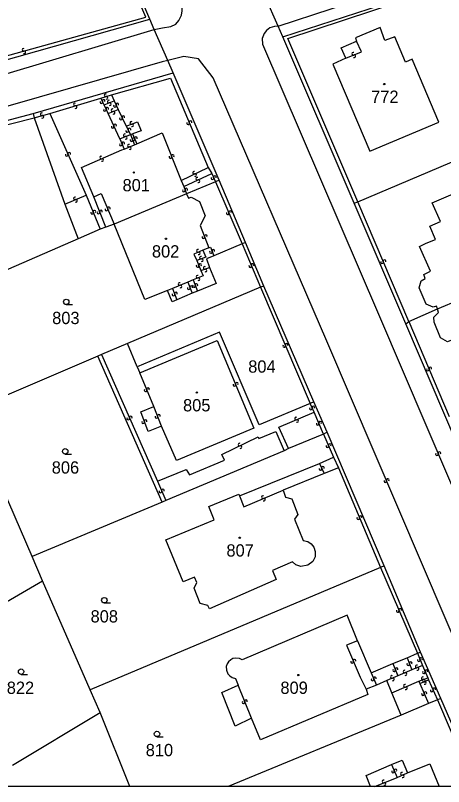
# Model space of a CAD drawing. Extents: x -600391 to -599491, y -1160176 to -1159402.
# Drawn here: x -599951.3 to -599892, y -1160176.1 to -1160069.3 of the extents above; entities that cross this region are included whole.
import ezdxf

# ---------------------------------------------------------------- set-up
doc = ezdxf.new("R2010")
doc.units = 0
for name, color, linetype in [('Level 1', 7, 'Continuous'), ('Level 13', 7, 'Continuous'), ('Level 3', 7, 'Continuous'), ('Level 4', 7, 'Continuous'), ('Level 5', 7, 'Continuous'), ('Vrstva 63', 7, 'Continuous')]:
    doc.layers.add(name, color=color, linetype=linetype)

msp = doc.modelspace()

# ---------------------------------------------------------------- linework, layer by layer
at = {"layer": 'Level 1'}
for p, q in [((-599887.13, -1160176.08), (-599892.35, -1160163.9)), ((-599935.46, -1160176.08), (-599939.58, -1160165.83)), ((-599897.88, -1160166.18), (-599921.81, -1160176.08))]:
    msp.add_line(p, q, dxfattribs=at)
for points in [[(-599932.7, -1160069.8), (-599940.17, -1160052.22)], [(-599914.24, -1160072.24), (-599890.32, -1160064.42), (-599879.7, -1160060.63), (-599875.46, -1160059.11)], [(-599914.89, -1160070.76), (-599916.7, -1160066.63)], [(-599966.81, -1160079.43), (-599932.7, -1160069.8)], [(-599932.07, -1160071.24), (-599932.7, -1160069.8)], [(-599914.24, -1160072.24), (-599914.89, -1160070.76)], [(-599905.51, -1160075.18), (-599907.33, -1160076.01), (-599902.19, -1160088.08), (-599892.63, -1160084.07), (-599896.35, -1160075.33), (-599897.24, -1160075.72), (-599898.76, -1160072.22), (-599900.11, -1160072.76), (-599900.78, -1160070.96), (-599904.19, -1160072.37), (-599904.06, -1160072.84)], [(-599930.21, -1160075.52), (-599932.07, -1160071.24)], [(-599904.37, -1160095.29), (-599914.24, -1160072.24)], [(-599905.51, -1160075.18), (-599906.19, -1160073.77), (-599904.06, -1160072.84)], [(-599929.47, -1160077.23), (-599930.21, -1160075.52)], [(-599948.86, -1160082.86), (-599929.47, -1160077.23)], [(-599923.07, -1160092.08), (-599929.47, -1160077.23)], [(-599903.88, -1160095.09), (-599867.15, -1160079.55)], [(-599967.37, -1160087.73), (-599948.86, -1160082.86)], [(-599948.86, -1160082.86), (-599948.69, -1160083.45)], [(-599948.69, -1160083.45), (-599944.46, -1160095.39)], [(-599923.59, -1160092.3), (-599927.61, -1160093.97)], [(-599923.07, -1160092.08), (-599923.59, -1160092.3)], [(-599919.42, -1160100.71), (-599923.07, -1160092.08)], [(-599892.82, -1160109.92), (-599892.99, -1160109.52), (-599893.45, -1160109.7), (-599894.41, -1160109.24), (-599895.35, -1160107), (-599895.07, -1160106.05), (-599894.52, -1160105.7), (-599894.72, -1160105.13), (-599893.81, -1160104.7), (-599895.32, -1160101.27), (-599894.41, -1160100.82), (-599893.12, -1160100.3), (-599893.91, -1160098.46), (-599892.4, -1160097.81), (-599893.55, -1160095.22), (-599887.76, -1160092.71), (-599885.76, -1160097.2)], [(-599927.61, -1160093.97), (-599937.64, -1160098.18)], [(-599944.46, -1160095.39), (-599942.6, -1160100.22)], [(-599904.37, -1160095.29), (-599903.88, -1160095.09)], [(-599897.21, -1160111.98), (-599904.37, -1160095.29)], [(-599939.54, -1160098.88), (-599942.6, -1160100.22)], [(-599938.8, -1160098.61), (-599939.54, -1160098.88)], [(-599937.64, -1160098.18), (-599938.8, -1160098.61)], [(-599930.25, -1160107.35), (-599933.38, -1160108.63), (-599937.64, -1160098.18)], [(-599942.6, -1160100.22), (-599961.96, -1160108.61)], [(-599919.87, -1160100.9), (-599923.82, -1160102.56)], [(-599919.42, -1160100.71), (-599919.87, -1160100.9)], [(-599916.87, -1160106.76), (-599919.42, -1160100.71)], [(-599923.82, -1160102.56), (-599924.84, -1160102.96), (-599924.4, -1160104.2)], [(-599924.4, -1160104.2), (-599923.5, -1160106.4), (-599926.1, -1160107.44)], [(-599892.82, -1160109.92), (-599883.54, -1160106.05)], [(-599917.33, -1160106.92), (-599935.76, -1160114.73)], [(-599928.92, -1160108.65), (-599929.58, -1160108.96), (-599930.25, -1160107.35)], [(-599926.1, -1160107.44), (-599926.8, -1160107.75)], [(-599916.87, -1160106.76), (-599917.33, -1160106.92)], [(-599909.98, -1160122.78), (-599916.87, -1160106.76)], [(-599926.8, -1160107.75), (-599928.92, -1160108.65)], [(-599896.79, -1160111.65), (-599892.82, -1160109.92)], [(-599897.21, -1160111.98), (-599896.79, -1160111.65)], [(-599890.2, -1160128.43), (-599897.21, -1160111.98)], [(-599910.46, -1160123.03), (-599917.53, -1160125.98), (-599923.02, -1160113.14), (-599934.43, -1160117.93)], [(-599935.76, -1160114.73), (-599939.38, -1160116.25)], [(-599934.43, -1160117.93), (-599935.76, -1160114.73)], [(-599939.9, -1160116.45), (-599957.71, -1160124.07)], [(-599939.38, -1160116.25), (-599939.9, -1160116.45)], [(-599930.98, -1160136.69), (-599939.9, -1160116.45)], [(-599909.98, -1160122.78), (-599910.46, -1160123.03)], [(-599908.1, -1160126.99), (-599909.98, -1160122.78)], [(-599908.6, -1160127.26), (-599913.49, -1160129.26)], [(-599908.1, -1160126.99), (-599908.6, -1160127.26)], [(-599900.24, -1160145.51), (-599908.1, -1160126.99)], [(-599948.99, -1160144.22), (-599955.5, -1160129.24)], [(-599914.07, -1160129.57), (-599930.47, -1160136.47)], [(-599913.49, -1160129.26), (-599914.07, -1160129.57)], [(-599909.2, -1160131.31), (-599907.23, -1160130.47)], [(-599907.23, -1160130.47), (-599906.56, -1160131.94)], [(-599920.24, -1160135.83), (-599909.2, -1160131.31)], [(-599906.56, -1160131.94), (-599908.55, -1160132.71)], [(-599908.55, -1160132.71), (-599914.23, -1160135.01)], [(-599914.23, -1160135.01), (-599913.89, -1160136), (-599913.02, -1160136.23), (-599912.19, -1160138.38), (-599912.64, -1160139.06), (-599911.44, -1160141.99), (-599910.81, -1160142.14), (-599910.34, -1160142.45), (-599909.97, -1160142.91), (-599909.76, -1160143.5), (-599909.8, -1160144.26), (-599910.11, -1160144.9), (-599910.78, -1160145.43), (-599911.75, -1160145.59), (-599912.44, -1160145.37), (-599912.92, -1160144.97), (-599915.67, -1160146.16), (-599915.16, -1160147.38), (-599924.42, -1160151.46), (-599924.65, -1160151.02), (-599925.69, -1160150.71), (-599926.55, -1160148.61), (-599926.15, -1160147.79), (-599926.5, -1160147.06), (-599928.07, -1160147.73), (-599930.48, -1160141.92), (-599923.75, -1160139.13), (-599924.49, -1160137.27), (-599920.33, -1160135.56), (-599920.24, -1160135.83)], [(-599930.98, -1160136.69), (-599948.99, -1160144.22)], [(-599930.47, -1160136.47), (-599930.98, -1160136.69)], [(-599947.56, -1160147.56), (-599948.99, -1160144.22)], [(-599900.73, -1160145.73), (-599940.94, -1160162.69)], [(-599900.24, -1160145.51), (-599900.73, -1160145.73)], [(-599895.17, -1160157.44), (-599900.24, -1160145.51)], [(-599961.7, -1160155.81), (-599947.56, -1160147.56)], [(-599940.94, -1160162.69), (-599947.56, -1160147.56)], [(-599903.91, -1160155.87), (-599905.35, -1160152.33), (-599919.9, -1160158.52), (-599920.28, -1160158.33), (-599920.75, -1160158.28), (-599921.17, -1160158.36), (-599921.48, -1160158.51), (-599921.77, -1160158.78), (-599921.97, -1160159.09), (-599922.09, -1160159.45), (-599922.08, -1160159.95), (-599921.88, -1160160.45), (-599921.61, -1160160.75), (-599921.26, -1160160.97), (-599920.83, -1160161.09), (-599920.46, -1160162.04)], [(-599903.91, -1160155.87), (-599902.04, -1160160.33)], [(-599897.05, -1160158.23), (-599895.61, -1160157.62)], [(-599895.61, -1160157.62), (-599895.17, -1160157.44)], [(-599892.35, -1160163.9), (-599895.17, -1160157.44)], [(-599899, -1160159.05), (-599897.05, -1160158.23)], [(-599902.04, -1160160.33), (-599899, -1160159.05)], [(-599899.83, -1160161.38), (-599901.27, -1160162.01)], [(-599899.14, -1160163.08), (-599899.83, -1160161.38)], [(-599939.58, -1160165.83), (-599940.94, -1160162.69)], [(-599918.6, -1160166.62), (-599920.86, -1160167.69), (-599922.73, -1160163.07), (-599920.46, -1160162.04)], [(-599902.72, -1160162.59), (-599902.47, -1160163.32), (-599917.36, -1160169.59), (-599918.6, -1160166.62)], [(-599901.27, -1160162.01), (-599902.72, -1160162.59)], [(-599897.88, -1160166.18), (-599899.14, -1160163.08)], [(-599892.83, -1160164.06), (-599894.09, -1160164.58)], [(-599892.35, -1160163.9), (-599892.83, -1160164.06)], [(-599894.09, -1160164.58), (-599897.88, -1160166.18)], [(-599951.71, -1160173.12), (-599939.58, -1160165.83)], [(-599899.19, -1160173.04), (-599897.74, -1160172.4), (-599896.97, -1160174.17)], [(-599902.11, -1160176.08), (-599902.72, -1160174.53), (-599899.19, -1160173.04)], [(-599896.97, -1160174.17), (-599893.87, -1160172.91), (-599892.58, -1160176.08)]]:
    msp.add_lwpolyline(points, dxfattribs=at)
at = {"layer": 'Level 13'}
for centre, start, end in [((-599950.18, -1160074.02), 52.9231, 285.0211), ((-599950.08, -1160074.38), 232.7086, 105.2986), ((-599904.5, -1160074.58), 59.2197, 291.3177), ((-599904.36, -1160074.92), 239.0052, 111.5952), ((-599938.81, -1160080.32), 55.3419, 287.4399), ((-599938.69, -1160080.68), 235.1274, 107.7174), ((-599943.07, -1160081.61), 53.8854, 285.9834), ((-599942.97, -1160081.97), 233.6709, 106.2609), ((-599939.4, -1160081.29), 155.4129, 27.5109), ((-599939.08, -1160081.11), 335.1984, 207.7884), ((-599938.38, -1160081.21), 59.6055, 291.7035), ((-599938.24, -1160081.55), 239.391, 111.981), ((-599937.52, -1160081.78), 151.9934, 24.5834), ((-599937.18, -1160081.62), 332.2079, 204.3059), ((-599947.67, -1160082.96), 53.4588, 285.5568), ((-599938.91, -1160082.33), 151.2022, 23.3002), ((-599938.57, -1160082.19), 330.9877, 203.5777), ((-599937.84, -1160082.41), 58.8205, 290.9185), ((-599937.7, -1160082.75), 238.606, 111.196), ((-599947.57, -1160083.32), 233.2444, 105.8344), ((-599936.69, -1160083.54), 152.7182, 25.3082), ((-599936.35, -1160083.38), 332.9327, 205.0307), ((-599935.25, -1160084.15), 57.7676, 289.8656), ((-599927.04, -1160084.07), 330.2581, 202.3561), ((-599937.83, -1160084.68), 152.4707, 24.5687), ((-599937.49, -1160084.52), 332.2562, 204.8462), ((-599935.5, -1160085.09), 336.2992, 208.3972), ((-599935.13, -1160084.49), 237.5532, 110.1432), ((-599927.38, -1160084.21), 150.0436, 22.6336), ((-599936.16, -1160085.87), 58.8441, 290.9421), ((-599936.02, -1160086.21), 238.6296, 111.2196), ((-599935.82, -1160085.27), 156.0847, 28.6747), ((-599934.61, -1160086.29), 331.024, 203.122), ((-599936.7, -1160087.13), 150.1163, 22.7063), ((-599936.36, -1160086.99), 330.3308, 202.4288), ((-599935.59, -1160087.31), 59.7932, 291.8912), ((-599935.24, -1160086.53), 147.7143, 20.3043), ((-599934.95, -1160086.43), 150.8096, 23.3996), ((-599934.9, -1160086.41), 327.9288, 200.0268), ((-599943.85, -1160088.43), 331.3352, 203.4332), ((-599935.45, -1160087.65), 239.5787, 112.1687), ((-599944.19, -1160088.57), 151.1208, 23.7108), ((-599939.42, -1160088.95), 60.8301, 292.9281), ((-599939.28, -1160089.29), 240.6157, 113.2057), ((-599929.84, -1160088.88), 148.8099, 21.3999), ((-599929.5, -1160088.74), 329.0243, 201.1223), ((-599926.56, -1160091.05), 62.647, 294.745), ((-599926.4, -1160091.39), 242.4325, 115.0225), ((-599926.12, -1160091.89), 61.9608, 294.0588), ((-599925.96, -1160092.23), 241.7463, 114.3363), ((-599924.01, -1160091.8), 151.4492, 24.0392), ((-599923.67, -1160091.66), 331.6637, 203.7617), ((-599927.97, -1160093.52), 147.5911, 20.1811), ((-599927.63, -1160093.4), 327.8056, 199.9036), ((-599943.05, -1160094.61), 59.7723, 291.8703), ((-599942.91, -1160094.95), 239.5579, 112.1479), ((-599940.69, -1160096.59), 149.7522, 22.3422), ((-599940.35, -1160096.45), 329.9667, 202.0647), ((-599939.79, -1160096.57), 148.5644, 20.6624), ((-599939.45, -1160096.43), 328.3499, 200.9399), ((-599938.69, -1160096.13), 149.7686, 22.3586), ((-599938.35, -1160095.99), 329.983, 202.081), ((-599921.9, -1160096.67), 150.5496, 23.1396), ((-599921.56, -1160096.53), 330.764, 202.862), ((-599925.27, -1160099.99), 148.8309, 21.4209), ((-599924.93, -1160099.85), 329.0453, 201.1433), ((-599926.03, -1160101.87), 61.6713, 294.2613), ((-599925.88, -1160102.21), 241.8857, 113.9837), ((-599924.23, -1160102.03), 148.7962, 21.3862), ((-599923.89, -1160101.89), 329.0107, 201.1087), ((-599925.6, -1160102.83), 57.8172, 290.4072), ((-599925.48, -1160103.17), 238.0316, 110.1296), ((-599900.17, -1160103.3), 330.336, 202.926), ((-599926.06, -1160103.97), 148.0828, 20.6728), ((-599925.72, -1160103.85), 328.2972, 200.3952), ((-599925.07, -1160104.22), 54.9652, 287.0632), ((-599918.77, -1160103.98), 150.0345, 22.6245), ((-599918.43, -1160103.84), 330.2489, 202.3469), ((-599900.51, -1160103.44), 150.5504, 22.6484), ((-599926.07, -1160105.45), 59.4554, 292.0454), ((-599924.97, -1160104.58), 234.7507, 107.3407), ((-599928.57, -1160106.47), 59.3759, 291.9659), ((-599926.23, -1160106.61), 328.3354, 200.4334), ((-599925.93, -1160105.79), 239.6699, 111.7679), ((-599928.43, -1160106.81), 239.5903, 111.6883), ((-599927.29, -1160107.05), 149.2776, 21.8676), ((-599926.95, -1160106.91), 329.4921, 201.5901), ((-599926.57, -1160106.74), 148.121, 20.711), ((-599929.41, -1160107.93), 149.2093, 21.7993), ((-599929.07, -1160107.79), 329.4238, 201.5218), ((-599914.07, -1160115.05), 150.2538, 22.8438), ((-599913.73, -1160114.91), 330.4682, 202.5662), ((-599893.83, -1160118.17), 330.3559, 202.4539), ((-599894.17, -1160118.31), 150.1414, 22.7314), ((-599920.63, -1160120.3), 330.1133, 202.2113), ((-599933.27, -1160121.19), 150.1237, 22.2217), ((-599932.93, -1160121.05), 329.9093, 202.4993), ((-599920.97, -1160120.44), 149.8989, 22.4889), ((-599910.03, -1160123.57), 330.8125, 203.4025), ((-599931.43, -1160124.73), 328.4494, 201.0394), ((-599910.37, -1160123.71), 151.0269, 23.1249), ((-599935.67, -1160125.09), 151.0237, 23.6137), ((-599935.33, -1160124.95), 331.2382, 203.3362), ((-599933.61, -1160125.6), 147.9983, 20.0963), ((-599933.27, -1160125.48), 327.7838, 200.3738), ((-599931.77, -1160124.87), 148.6639, 20.7619), ((-599912.43, -1160125.1), 60.4431, 292.5411), ((-599912.29, -1160125.44), 240.2287, 112.8187), ((-599909.09, -1160125.68), 330.9268, 203.5168), ((-599909.43, -1160125.82), 151.1413, 23.2393), ((-599920.27, -1160128.71), 63.4776, 295.5756), ((-599908.09, -1160128.93), 150.2706, 22.8606), ((-599907.75, -1160128.79), 330.4851, 202.5831), ((-599920.11, -1160129.05), 243.2631, 115.8531), ((-599892.57, -1160129.9), 330.557, 202.655), ((-599892.91, -1160130.04), 150.3425, 22.9325), ((-599909.05, -1160132.09), 152.063, 24.653), ((-599908.71, -1160131.93), 332.2775, 204.3755), ((-599900.05, -1160133.76), 150.5463, 22.6443), ((-599899.71, -1160133.62), 330.3318, 202.9218), ((-599931.21, -1160135.2), 150.3827, 22.9727), ((-599930.87, -1160135.06), 330.5971, 202.6951), ((-599917.01, -1160135.99), 60.405, 292.503), ((-599916.87, -1160136.33), 240.1905, 112.7805), ((-599903.81, -1160138.91), 150.0755, 22.6655), ((-599903.47, -1160138.77), 330.2899, 202.3879), ((-599898.34, -1160151.75), 150.4557, 23.0457), ((-599898, -1160151.61), 330.6701, 202.7681), ((-599904.66, -1160158.78), 150.3879, 22.9779), ((-599904.32, -1160158.64), 330.6024, 202.7004), ((-599895.43, -1160158.55), 149.4203, 22.0103), ((-599895.09, -1160158.41), 329.6348, 201.7328), ((-599898.49, -1160159.83), 329.291, 201.389), ((-599896.88, -1160159.13), 149.4342, 22.0242), ((-599896.54, -1160158.99), 329.6486, 201.7466), ((-599895.71, -1160159.44), 58.1432, 290.7332), ((-599895.58, -1160159.78), 238.3576, 110.4556), ((-599899.14, -1160160.89), 60.1275, 292.7175), ((-599898.83, -1160159.97), 149.0765, 21.6665), ((-599897.41, -1160160.15), 60.7105, 293.3005), ((-599897.27, -1160160.49), 240.925, 113.023), ((-599894.87, -1160161.08), 58.6004, 290.6984), ((-599894.72, -1160160.25), 150.234, 22.824), ((-599894.38, -1160160.11), 330.4485, 202.5465), ((-599901.83, -1160161.25), 151.7818, 24.3718), ((-599901.49, -1160161.09), 331.9963, 204.0943), ((-599899, -1160161.23), 240.342, 112.44), ((-599897.34, -1160162.12), 60.4047, 292.5027), ((-599894.73, -1160161.39), 60.5713, 292.6693), ((-599894.73, -1160161.42), 238.3859, 110.9759), ((-599894.59, -1160161.73), 240.3569, 112.9469), ((-599897.2, -1160162.46), 240.1903, 112.7803), ((-599894.51, -1160163.13), 330.3455, 202.4435), ((-599893.62, -1160162.75), 151.4293, 24.0193), ((-599893.28, -1160162.61), 331.6438, 203.7418), ((-599919.36, -1160164.26), 329.261, 201.851), ((-599894.85, -1160163.27), 150.131, 22.721), ((-599919.7, -1160164.4), 149.4755, 21.5735), ((-599898.65, -1160173.85), 330.4534, 202.5513), ((-599898.99, -1160173.99), 150.2389, 22.8289), ((-599897.78, -1160174.31), 60.5713, 292.6693), ((-599897.64, -1160174.65), 240.3569, 112.9469), ((-599900.31, -1160175.37), 59.9132, 292.0112), ((-599900.17, -1160175.71), 239.6988, 112.2888)]:
    msp.add_arc(centre, 0.184, start, end, dxfattribs=at)
at = {"layer": 'Level 3'}
for p, q in [((-599892.83, -1160164.06), (-599887.73, -1160176.08)), ((-599901.52, -1160176.08), (-599898.44, -1160174.8))]:
    msp.add_line(p, q, dxfattribs=at)
for points in [[(-599932.07, -1160071.24), (-599930.91, -1160071.01), (-599929.76, -1160070.79), (-599929.09, -1160070.48), (-599928.67, -1160069.97), (-599928.31, -1160069.23), (-599928.2, -1160068.62), (-599928.16, -1160067.74), (-599944.31, -1160030.32), (-599957.81, -1159998.89), (-599969.74, -1159971.09), (-599971.59, -1159969.36), (-599973.79, -1159968.78), (-599975.69, -1159969.42)], [(-599914.89, -1160070.76), (-599907.55, -1160068.37), (-599900.91, -1160066.15), (-599873.39, -1160056.47), (-599862.7, -1160052.44), (-599839.71, -1160043.28), (-599838.86, -1160042.68)], [(-599967.02, -1160078.9), (-599933.24, -1160069.5), (-599940.38, -1160052.87)], [(-599903.88, -1160095.09), (-599913.57, -1160072.45), (-599890.16, -1160064.71), (-599879.57, -1160060.98), (-599875.41, -1160059.5)], [(-599914.89, -1160070.76), (-599915.43, -1160070.79), (-599916.05, -1160071.01), (-599916.5, -1160071.34), (-599916.83, -1160071.76), (-599917.11, -1160072.47), (-599917.09, -1160073.24), (-599901.01, -1160110.66), (-599884.47, -1160149.28), (-599878.82, -1160162.53), (-599872.95, -1160176.08)], [(-600027.74, -1160093.03), (-600026.82, -1160093.42), (-600025.86, -1160093.71), (-600021.64, -1160093.67), (-600010.66, -1160091.41), (-599968.6, -1160081.73), (-599953.35, -1160077.6), (-599932.07, -1160071.24)], [(-599905.51, -1160075.18), (-599903.34, -1160074.31), (-599904.06, -1160072.84)], [(-599881.72, -1160176.08), (-599891.61, -1160153.01), (-599908.15, -1160114.37), (-599923.89, -1160077.89), (-599925.96, -1160075.27), (-599927.96, -1160074.98), (-599930.21, -1160075.52)], [(-599930.21, -1160075.52), (-599930.99, -1160075.71), (-599952.34, -1160081.82), (-599967.7, -1160085.82), (-600009.32, -1160095.04), (-600022.67, -1160102.5), (-600023.09, -1160102.76)], [(-599938.01, -1160080.26), (-599929.82, -1160077.94), (-599924.59, -1160090.33)], [(-599946.54, -1160082.83), (-599939.49, -1160080.74)], [(-599939.49, -1160080.74), (-599938.01, -1160080.26)], [(-599939, -1160081.66), (-599939.49, -1160080.74)], [(-599938.01, -1160080.26), (-599937.63, -1160081.1)], [(-599939, -1160081.66), (-599937.63, -1160081.1)], [(-599938.47, -1160082.86), (-599939, -1160081.66)], [(-599937.63, -1160081.1), (-599937.07, -1160082.31)], [(-599948.69, -1160083.45), (-599946.54, -1160082.83)], [(-599946.54, -1160082.83), (-599941.5, -1160094.17)], [(-599938.47, -1160082.86), (-599937.07, -1160082.31)], [(-599936.84, -1160086.34), (-599938.47, -1160082.86)], [(-599937.07, -1160082.31), (-599935.97, -1160084.61)], [(-599967.31, -1160088.16), (-599948.69, -1160083.45)], [(-599935.97, -1160084.61), (-599934.41, -1160084.03), (-599933.89, -1160085.25), (-599935.08, -1160085.67)], [(-599935.97, -1160084.61), (-599935.34, -1160085.75)], [(-599936.84, -1160086.34), (-599935.34, -1160085.75)], [(-599935.34, -1160085.75), (-599935.08, -1160085.67)], [(-599935.34, -1160085.75), (-599934.8, -1160087.19)], [(-599935.08, -1160085.67), (-599934.48, -1160087.04)], [(-599934.48, -1160087.04), (-599930.98, -1160085.51), (-599928.36, -1160092.11)], [(-599936.84, -1160086.34), (-599936.23, -1160087.78)], [(-599936.23, -1160087.78), (-599934.8, -1160087.19)], [(-599934.8, -1160087.19), (-599934.48, -1160087.04)], [(-599940.44, -1160094.38), (-599942.15, -1160090.33), (-599936.55, -1160087.9), (-599936.23, -1160087.78)], [(-599928.36, -1160092.11), (-599924.59, -1160090.33)], [(-599924.59, -1160090.33), (-599924.1, -1160091.17)], [(-599927.99, -1160092.95), (-599924.1, -1160091.17)], [(-599924.1, -1160091.17), (-599923.59, -1160092.3)], [(-599928.36, -1160092.11), (-599927.99, -1160092.95)], [(-599923.59, -1160092.3), (-599919.87, -1160100.9)], [(-599927.99, -1160092.95), (-599927.61, -1160093.97)], [(-599944.46, -1160095.39), (-599941.5, -1160094.17)], [(-599941.5, -1160094.17), (-599939.54, -1160098.88)], [(-599940.44, -1160094.38), (-599939.41, -1160093.93), (-599937.64, -1160098.18)], [(-599938.8, -1160098.61), (-599940.44, -1160094.38)], [(-599927.61, -1160093.97), (-599927.31, -1160094.58), (-599926.95, -1160094.43), (-599925.8, -1160095.02), (-599925.02, -1160097.01), (-599925.71, -1160098.38), (-599924.49, -1160101.45)], [(-599896.79, -1160111.65), (-599903.88, -1160095.09)], [(-599919.87, -1160100.9), (-599917.33, -1160106.92)], [(-599925.32, -1160101.76), (-599926.57, -1160102.33), (-599926.15, -1160103.23)], [(-599925.32, -1160101.76), (-599924.93, -1160102.77), (-599926.15, -1160103.23)], [(-599924.49, -1160101.45), (-599925.32, -1160101.76)], [(-599924.49, -1160101.45), (-599924.3, -1160101.35), (-599923.82, -1160102.56)], [(-599926.15, -1160103.23), (-599925.63, -1160104.59)], [(-599925.63, -1160104.59), (-599924.4, -1160104.2)], [(-599925.63, -1160104.59), (-599925.3, -1160105.33), (-599926.69, -1160105.9)], [(-599927.43, -1160106.2), (-599929.56, -1160107.07)], [(-599926.69, -1160105.9), (-599927.43, -1160106.2)], [(-599927.43, -1160106.2), (-599926.8, -1160107.75)], [(-599926.69, -1160105.9), (-599926.1, -1160107.44)], [(-599929.56, -1160107.07), (-599930.25, -1160107.35)], [(-599929.56, -1160107.07), (-599928.92, -1160108.65)], [(-599917.33, -1160106.92), (-599910.46, -1160123.03)], [(-599885.93, -1160117.4), (-599886.05, -1160117.06), (-599888.14, -1160117.9), (-599889.67, -1160114.41), (-599890.6, -1160114.85), (-599890.89, -1160114.25), (-599891.46, -1160114.5), (-599892.41, -1160113.94), (-599893.3, -1160111.75), (-599893.35, -1160111.05), (-599892.67, -1160110.4), (-599892.82, -1160109.92)], [(-599896.79, -1160111.65), (-599891.2, -1160124.83)], [(-599934.08, -1160118.79), (-599923.34, -1160114.31), (-599918.26, -1160126.43), (-599928.97, -1160130.91), (-599931.07, -1160126.16)], [(-599939.38, -1160116.25), (-599931.62, -1160133.79)], [(-599934.43, -1160117.93), (-599934.08, -1160118.79)], [(-599932.13, -1160123.44), (-599934.08, -1160118.79)], [(-599931.07, -1160126.16), (-599932.93, -1160126.89), (-599933.95, -1160124.18), (-599932.13, -1160123.44)], [(-599931.07, -1160126.16), (-599932.13, -1160123.44)], [(-599909.93, -1160124.24), (-599910.46, -1160123.03)], [(-599913.49, -1160129.26), (-599914.79, -1160126.31), (-599909.93, -1160124.24)], [(-599908.6, -1160127.26), (-599909.93, -1160124.24)], [(-599931.62, -1160133.79), (-599927.63, -1160132.18), (-599927.19, -1160132.89), (-599922.36, -1160130.87), (-599922.69, -1160130.1), (-599917.69, -1160127.65), (-599917.59, -1160127.87), (-599915.24, -1160126.92), (-599914.07, -1160129.57)], [(-599908.6, -1160127.26), (-599907.23, -1160130.47)], [(-599909.2, -1160131.31), (-599908.55, -1160132.71)], [(-599906.56, -1160131.94), (-599900.73, -1160145.73)], [(-599931.62, -1160133.79), (-599930.47, -1160136.47)], [(-599920.24, -1160135.83), (-599919.64, -1160137.31), (-599914.23, -1160135.01)], [(-599900.73, -1160145.73), (-599895.61, -1160157.62)], [(-599903.91, -1160155.87), (-599905.44, -1160156.49), (-599903.53, -1160160.94), (-599902.72, -1160162.59)], [(-599895.61, -1160157.62), (-599894.91, -1160159.33)], [(-599897.05, -1160158.23), (-599896.37, -1160159.89)], [(-599899, -1160159.05), (-599898.32, -1160160.74)], [(-599894.91, -1160159.33), (-599896.37, -1160159.89)], [(-599894.91, -1160159.33), (-599894.19, -1160161.02)], [(-599902.04, -1160160.33), (-599901.27, -1160162.01)], [(-599898.32, -1160160.74), (-599899.83, -1160161.38)], [(-599896.37, -1160159.89), (-599898.32, -1160160.74)], [(-599899.14, -1160163.08), (-599895.4, -1160161.49)], [(-599895.4, -1160161.49), (-599894.19, -1160161.02)], [(-599895.4, -1160161.49), (-599895.26, -1160161.82)], [(-599895.26, -1160161.82), (-599894.07, -1160161.31)], [(-599895.26, -1160161.82), (-599894.09, -1160164.58)], [(-599894.19, -1160161.02), (-599894.07, -1160161.31)], [(-599894.07, -1160161.31), (-599892.83, -1160164.06)], [(-599918.6, -1160166.62), (-599920.46, -1160162.04)], [(-599899.19, -1160173.04), (-599898.44, -1160174.8)], [(-599898.44, -1160174.8), (-599896.97, -1160174.17)]]:
    msp.add_lwpolyline(points, dxfattribs=at)
at = {"layer": 'Level 5'}
for p, q in [((-599944.26, -1160109.32), (-599943.39, -1160109.32)), ((-599944.4, -1160130.03), (-599943.53, -1160130.03)), ((-599938.99, -1160150.65), (-599938.11, -1160150.65)), ((-599950.52, -1160160.54), (-599949.65, -1160160.54)), ((-599931.69, -1160169.17), (-599930.82, -1160169.17))]:
    msp.add_line(p, q, dxfattribs=at)
for centre, radius in [((-599900.2, -1160078.78), 0.09), ((-599900.2, -1160078.78), 0.0521), ((-599934.9, -1160091.03), 0.09), ((-599934.9, -1160091.03), 0.0521), ((-599930.45, -1160100.2), 0.09), ((-599930.45, -1160100.2), 0.0521), ((-599944.26, -1160108.94), 0.375), ((-599926.17, -1160121.51), 0.09), ((-599926.17, -1160121.51), 0.0521), ((-599944.4, -1160129.65), 0.375), ((-599920.23, -1160141.62), 0.09), ((-599920.23, -1160141.62), 0.0521), ((-599938.99, -1160150.27), 0.375), ((-599950.52, -1160160.16), 0.375), ((-599912.11, -1160160.63), 0.09), ((-599912.11, -1160160.63), 0.0521), ((-599931.69, -1160168.79), 0.375)]:
    msp.add_circle(centre, radius, dxfattribs=at)
at = {"layer": 'Vrstva 63'}
msp.add_lwpolyline([(-600391.01, -1159401.77), (-599490.77, -1159401.77), (-599490.77, -1160176.08), (-600391.01, -1160176.08)], close=True, dxfattribs=at)

# ---------------------------------------------------------------- texts
at = {"layer": 'Level 4'}
for s, p in [('772', (-599902.02, -1160081.38)), ('801', (-599936.46, -1160093.63)), ('802', (-599932.39, -1160102.8)), ('803', (-599946.21, -1160112.02)), ('804', (-599919.05, -1160118.75)), ('805', (-599928.08, -1160124.11)), ('806', (-599946.27, -1160132.73)), ('807', (-599922.07, -1160144.22)), ('808', (-599940.89, -1160153.35)), ('822', (-599952.5, -1160163.24)), ('809', (-599914.59, -1160163.24)), ('810', (-599933.25, -1160171.87))]:
    msp.add_text(s, height=1.7, dxfattribs=at).set_placement(p)

doc.saveas('drawing.dxf')
